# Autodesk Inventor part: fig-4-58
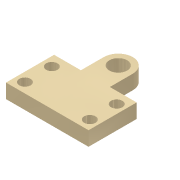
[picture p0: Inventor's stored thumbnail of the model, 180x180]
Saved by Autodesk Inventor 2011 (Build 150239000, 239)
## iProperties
Created: 2004-05
Part Number: fig-4-58
Document SubType Name: Modeling
Designer: CADCIM Technologies
Manufacturer: Standard
Standards Organization: Custom
Density: 1 g/cm^3
Author: CADCIM Technologies
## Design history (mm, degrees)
sketch "Sketch1"
  geometry: L1 (39.729, 55.62)-(39.729, 42.054); L2 (39.729, 42.054)-(23.837, 42.054); L3 (23.837, 42.054)-(23.837, 13.516); L4 (23.837, 13.516)-(72.804, 13.516); L5 (72.804, 13.516)-(72.804, 42.054); L6 (72.804, 42.054)-(56.912, 42.054); L7 (56.912, 42.054)-(56.912, 55.62); C1 r 3.354 at (29.212, 35.336); C2 r 3.354 at (29.212, 19.383); C3 r 3.354 at (67.7, 35.336); C4 r 3.354 at (67.7, 19.383); C5 r 5.297 at (48.32, 55.62); A1 r 8.592 centre (48.32, 55.62) between (56.912, 55.62) and (39.729, 55.62)
  constraints: 14 end point, 6 centre point, 4 parallel, 2 equal length, 2 horizontal alignment, 2 point on circle, 2 tangent, 2 vertical alignment, 1 coincident, 1 collinear, 1 perpendicular, 1 vertical
extrude "Extrusion1" new body sketch "Sketch1" distance "d0" = 8.5; taper "d1" = 0 deg
body "Solid1"
